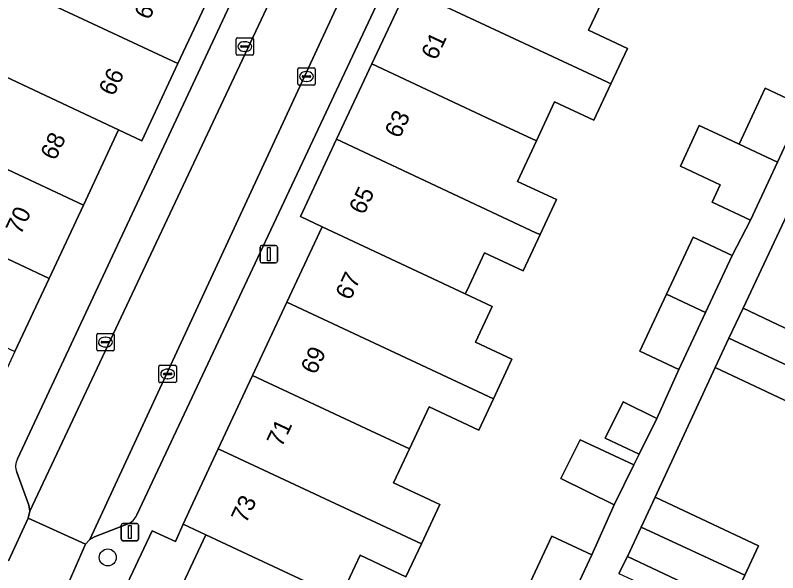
# Model space of a CAD drawing. Extents: x 159817 to 160765, y 380688 to 381638.
# Drawn here: x 160176.21 to 160219.96, y 381290.64 to 381322.59 of the extents above; entities that cross this region are included whole.
import ezdxf

# ---------------------------------------------------------------- set-up
doc = ezdxf.new("R2010")
doc.units = 0
for name, color, linetype in [('IMGEO_Boom', 7, 'Continuous'), ('IMGEO_Erf', 7, 'Continuous'), ('IMGEO_Kolk', 7, 'Continuous'), ('IMGEO_Lichtmast', 7, 'Continuous'), ('IMGEO_Pand', 7, 'Continuous'), ('IMGEO_Pand_nummerreeks', 7, 'Continuous'), ('IMGEO_Parkeervlak_open', 7, 'Continuous'), ('IMGEO_Rijbaan_lokaal_open', 7, 'Continuous'), ('IMGEO_Voetpad_halfverhard', 7, 'Continuous'), ('IMGEO_Voetpad_open', 7, 'Continuous')]:
    doc.layers.add(name, color=color, linetype=linetype)

msp = doc.modelspace()

# ---------------------------------------------------------------- linework, layer by layer
at = {"layer": 'IMGEO_Boom'}
msp.add_circle((160181.516, 381291.514), 0.489, dxfattribs=at)
at = {"layer": 'IMGEO_Erf'}
for points in [[(160210.219, 381324.135), (160209.096, 381321.736), (160211.329, 381320.69), (160210.378, 381318.659), (160209.402, 381316.572), (160207.155, 381317.624), (160206.109, 381315.388), (160205.024, 381313.07), (160207.262, 381312.023), (160206.323, 381310.016), (160205.351, 381307.94), (160203.135, 381308.978), (160202.134, 381306.839), (160202.032, 381306.621), (160203.579, 381305.897), (160202.621, 381303.849), (160204.701, 381302.875), (160203.64, 381300.609), (160202.801, 381298.816), (160199.952, 381300.149), (160198.823, 381297.736), (160197.91, 381295.786), (160200.564, 381294.544), (160199.508, 381292.288), (160198.627, 381290.404), (160195.996, 381291.635), (160194.857, 381289.201)], [(160205.49, 381289.504), (160206.996, 381292.73), (160209.288, 381291.66), (160210.564, 381294.523), (160207.515, 381296.031), (160208.619, 381298.262), (160211.7, 381296.821), (160212.003, 381297.433), (160210.062, 381298.341), (160211.094, 381300.43), (160213.015, 381299.48), (160214.292, 381302.283), (160212.052, 381303.329), (160213.58, 381306.604), (160215.101, 381309.866), (160217.343, 381308.82), (160218.39, 381310.842), (160216.188, 381311.87), (160216.657, 381312.876), (160214.37, 381313.946), (160215.456, 381316.273), (160217.053, 381315.525), (160217.743, 381315.202), (160219.238, 381318.406), (160221.44, 381317.379)], [(160221.405, 381313.09), (160217.965, 381305.792), (160223.888, 381303.001)], [(160222.288, 381299.605), (160216.365, 381302.397), (160212.932, 381294.963), (160218.855, 381292.172), (160218.063, 381290.492), (160217.255, 381288.776), (160211.332, 381291.567), (160210.842, 381290.6), (160212.59, 381289.786), (160211.501, 381287.444), (160209.752, 381288.257), (160207.732, 381284.025), (160213.443, 381281.353), (160212.775, 381279.925), (160212.092, 381278.466), (160206.381, 381281.138), (160205.548, 381279.354), (160209.884, 381277.322), (160208.887, 381275.196), (160204.6, 381277.205), (160204.565, 381277.114), (160225.954, 381267.134)]]:
    msp.add_lwpolyline(points, dxfattribs=at)
msp.add_lwpolyline([(160190.736, 381283.488), (160191.63, 381285.397), (160185.096, 381288.454), (160187.137, 381292.815), (160185.833, 381293.425), (160185.402, 381292.422), (160184.059, 381293.029), (160182.154, 381288.991), (160182.804, 381287.168)], close=True, dxfattribs=at)
at = {"layer": 'IMGEO_Kolk'}
for p, q in [((160188.881, 381320.372), (160188.881, 381321.224)), ((160188.956, 381321.298), (160189.808, 381321.298)), ((160189.882, 381321.224), (160189.882, 381320.372)), ((160189.14, 381320.792), (160189.14, 381320.804)), ((160189.578, 381320.755), (160189.18, 381320.755)), ((160189.183, 381320.841), (160189.581, 381320.841)), ((160189.369, 381321.078), (160189.394, 381321.078)), ((160189.624, 381320.804), (160189.624, 381320.792)), ((160189.808, 381320.298), (160188.956, 381320.298)), ((160189.392, 381320.518), (160189.367, 381320.518)), ((160192.415, 381318.657), (160192.415, 381319.509)), ((160192.49, 381319.583), (160193.342, 381319.583)), ((160192.903, 381319.363), (160192.928, 381319.363)), ((160193.416, 381319.509), (160193.416, 381318.657)), ((160192.674, 381319.077), (160192.674, 381319.089)), ((160193.112, 381319.04), (160192.714, 381319.04)), ((160192.717, 381319.126), (160193.115, 381319.126)), ((160193.158, 381319.089), (160193.158, 381319.077)), ((160193.342, 381318.583), (160192.49, 381318.583)), ((160192.926, 381318.803), (160192.901, 381318.803)), ((160180.879, 381303.429), (160180.879, 381304.281)), ((160180.954, 381304.355), (160181.806, 381304.355)), ((160181.367, 381304.135), (160181.392, 381304.135)), ((160181.88, 381304.281), (160181.88, 381303.429)), ((160181.138, 381303.849), (160181.138, 381303.861)), ((160181.576, 381303.812), (160181.178, 381303.812)), ((160181.181, 381303.898), (160181.579, 381303.898)), ((160181.622, 381303.861), (160181.622, 381303.849)), ((160181.806, 381303.355), (160180.954, 381303.355)), ((160181.39, 381303.575), (160181.365, 381303.575)), ((160184.45, 381301.605), (160184.45, 381302.457)), ((160184.525, 381302.531), (160185.377, 381302.531)), ((160184.938, 381302.311), (160184.963, 381302.311)), ((160185.451, 381302.457), (160185.451, 381301.605)), ((160184.709, 381302.025), (160184.709, 381302.037)), ((160185.147, 381301.988), (160184.749, 381301.988)), ((160184.752, 381302.074), (160185.15, 381302.074)), ((160185.193, 381302.037), (160185.193, 381302.025)), ((160185.377, 381301.531), (160184.525, 381301.531)), ((160184.961, 381301.751), (160184.936, 381301.751))]:
    msp.add_line(p, q, dxfattribs=at)
for points in [[(160188.881, 381320.372), (160188.881, 381321.224)], [(160188.956, 381321.298), (160189.808, 381321.298)], [(160189.882, 381321.224), (160189.882, 381320.372)], [(160189.808, 381320.298), (160188.956, 381320.298)], [(160192.415, 381318.657), (160192.415, 381319.509)], [(160192.49, 381319.583), (160193.342, 381319.583)], [(160193.416, 381319.509), (160193.416, 381318.657)], [(160193.342, 381318.583), (160192.49, 381318.583)], [(160180.879, 381303.429), (160180.879, 381304.281)], [(160180.954, 381304.355), (160181.806, 381304.355)], [(160181.88, 381304.281), (160181.88, 381303.429)], [(160181.806, 381303.355), (160180.954, 381303.355)], [(160184.45, 381301.605), (160184.45, 381302.457)], [(160184.525, 381302.531), (160185.377, 381302.531)], [(160185.451, 381302.457), (160185.451, 381301.605)], [(160185.377, 381301.531), (160184.525, 381301.531)]]:
    msp.add_lwpolyline(points, dxfattribs=at)
for centre, radius, start, end in [((160188.958, 381321.222), 0.0765, 91.552, 178.448), ((160188.958, 381321.222), 0.0765, 91.552, 178.448), ((160189.806, 381321.222), 0.0765, 1.552, 88.448), ((160189.806, 381321.222), 0.0765, 1.552, 88.448), ((160189.18, 381320.801), 0.0403, 85.8775, 175.7526), ((160189.177, 381320.791), 0.0366, 178.938, 274.7102), ((160189.581, 381320.798), 0.043, 264.8664, 352.4533), ((160189.585, 381320.803), 0.0386, 1.7309, 96.639), ((160188.958, 381320.374), 0.0765, 181.552, 268.448), ((160188.958, 381320.374), 0.0765, 181.552, 268.448), ((160189.806, 381320.374), 0.0765, 271.552, 358.448), ((160189.806, 381320.374), 0.0765, 271.552, 358.448), ((160192.492, 381319.507), 0.0765, 91.552, 178.448), ((160192.492, 381319.507), 0.0765, 91.552, 178.448), ((160193.34, 381319.507), 0.0765, 1.552, 88.448), ((160193.34, 381319.507), 0.0765, 1.552, 88.448), ((160192.714, 381319.086), 0.0403, 85.8775, 175.7526), ((160192.711, 381319.076), 0.0366, 178.938, 274.7102), ((160193.115, 381319.083), 0.043, 264.8664, 352.4533), ((160193.119, 381319.088), 0.0386, 1.7309, 96.639), ((160192.492, 381318.659), 0.0765, 181.552, 268.448), ((160192.492, 381318.659), 0.0765, 181.552, 268.448), ((160193.34, 381318.659), 0.0765, 271.552, 358.448), ((160193.34, 381318.659), 0.0765, 271.552, 358.448), ((160180.956, 381304.279), 0.0765, 91.552, 178.448), ((160180.956, 381304.279), 0.0765, 91.552, 178.448), ((160181.804, 381304.279), 0.0765, 1.552, 88.448), ((160181.804, 381304.279), 0.0765, 1.552, 88.448), ((160181.178, 381303.858), 0.0403, 85.8775, 175.7526), ((160181.175, 381303.848), 0.0366, 178.938, 274.7102), ((160181.579, 381303.855), 0.043, 264.8664, 352.4533), ((160181.583, 381303.86), 0.0386, 1.7309, 96.639), ((160180.956, 381303.431), 0.0765, 181.552, 268.448), ((160180.956, 381303.431), 0.0765, 181.552, 268.448), ((160181.804, 381303.431), 0.0765, 271.552, 358.448), ((160181.804, 381303.431), 0.0765, 271.552, 358.448), ((160184.527, 381302.455), 0.0765, 91.552, 178.448), ((160184.527, 381302.455), 0.0765, 91.552, 178.448), ((160185.375, 381302.455), 0.0765, 1.552, 88.448), ((160185.375, 381302.455), 0.0765, 1.552, 88.448), ((160184.749, 381302.034), 0.0403, 85.8775, 175.7526), ((160184.746, 381302.024), 0.0366, 178.938, 274.7102), ((160185.15, 381302.031), 0.043, 264.8664, 352.4533), ((160185.154, 381302.036), 0.0386, 1.7309, 96.639), ((160184.527, 381301.607), 0.0765, 181.552, 268.448), ((160184.527, 381301.607), 0.0765, 181.552, 268.448), ((160185.375, 381301.607), 0.0765, 271.552, 358.448), ((160185.375, 381301.607), 0.0765, 271.552, 358.448)]:
    msp.add_arc(centre, radius, start, end, dxfattribs=at)
for centre, major_axis, ratio, start_param, end_param in [((160189.368, 381320.798), (-0.387, 0.002), 0.722429, 4.712389, 7.853982), ((160189.393, 381320.798), (-0.39, 0.002), 0.717154, 1.570796, 4.712389), ((160192.902, 381319.083), (-0.387, 0.002), 0.722429, 4.712389, 7.853982), ((160192.927, 381319.083), (-0.39, 0.002), 0.717154, 1.570796, 4.712389), ((160181.366, 381303.855), (-0.387, 0.002), 0.722429, 4.712389, 7.853982), ((160181.391, 381303.855), (-0.39, 0.002), 0.717154, 1.570796, 4.712389), ((160184.937, 381302.031), (-0.387, 0.002), 0.722429, 4.712389, 7.853982), ((160184.962, 381302.031), (-0.39, 0.002), 0.717154, 1.570796, 4.712389)]:
    msp.add_ellipse(centre, major_axis=major_axis, ratio=ratio, start_param=start_param, end_param=end_param, dxfattribs=at)
at = {"layer": 'IMGEO_Lichtmast'}
for p, q in [((160190.258, 381308.498), (160190.258, 381309.298)), ((160190.258, 381309.298), (160190.258, 381308.498)), ((160190.358, 381309.398), (160191.148, 381309.398)), ((160191.148, 381309.398), (160190.358, 381309.398)), ((160191.248, 381309.298), (160191.248, 381308.498)), ((160191.248, 381308.498), (160191.248, 381309.298)), ((160191.148, 381308.398), (160190.358, 381308.398)), ((160190.358, 381308.398), (160191.148, 381308.398)), ((160182.283, 381292.566), (160182.283, 381293.366)), ((160182.283, 381293.366), (160182.283, 381292.566)), ((160182.383, 381293.466), (160183.173, 381293.466)), ((160183.173, 381293.466), (160182.383, 381293.466)), ((160183.273, 381293.366), (160183.273, 381292.566)), ((160183.273, 381292.566), (160183.273, 381293.366)), ((160183.173, 381292.466), (160182.383, 381292.466)), ((160182.383, 381292.466), (160183.173, 381292.466))]:
    msp.add_line(p, q, dxfattribs=at)
for points in [[(160190.678, 381309.273), (160190.828, 381309.273), (160190.828, 381308.523), (160190.678, 381308.523), (160190.678, 381309.273)], [(160182.703, 381293.341), (160182.853, 381293.341), (160182.853, 381292.591), (160182.703, 381292.591), (160182.703, 381293.341)]]:
    msp.add_lwpolyline(points, dxfattribs=at)
for centre, start, end in [((160190.358, 381309.298), 90, 180), ((160190.358, 381309.298), 90, 180), ((160191.148, 381309.298), 0, 90), ((160191.148, 381309.298), 360, 90), ((160190.358, 381308.498), 180, 270), ((160190.358, 381308.498), 180, 270), ((160191.148, 381308.498), 270, 0), ((160191.148, 381308.498), 270, 0), ((160182.383, 381293.366), 90, 180), ((160182.383, 381293.366), 90, 180), ((160183.173, 381293.366), 0, 90), ((160183.173, 381293.366), 360, 90), ((160182.383, 381292.566), 180, 270), ((160182.383, 381292.566), 180, 270), ((160183.173, 381292.566), 270, 0), ((160183.173, 381292.566), 270, 0)]:
    msp.add_arc(centre, 0.1, start, end, dxfattribs=at)
at = {"layer": 'IMGEO_Pand'}
for points in [[(160173.791, 381325.318), (160185.534, 381319.826), (160187.554, 381324.142), (160180.701, 381327.347), (160178.108, 381328.56), (160177.087, 381326.378), (160174.79, 381327.453)], [(160203.421, 381327.319), (160200.76, 381328.565), (160198.686, 381324.132), (160210.143, 381318.769), (160210.378, 381318.659), (160211.329, 381320.69), (160209.096, 381321.736), (160210.219, 381324.135)], [(160185.534, 381319.826), (160173.791, 381325.318), (160172.873, 381323.355), (160174.016, 381322.82), (160172.867, 381320.363), (160175.321, 381319.214), (160182.134, 381316.022), (160183.463, 381315.401)], [(160210.378, 381318.659), (160210.143, 381318.769), (160198.686, 381324.132), (160196.663, 381319.809), (160203.273, 381316.715), (160206.109, 381315.388), (160207.155, 381317.624), (160209.402, 381316.572)], [(160180.118, 381311.714), (160182.134, 381316.022), (160175.321, 381319.214), (160172.867, 381320.363), (160171.913, 381318.324), (160169.419, 381319.491), (160168.355, 381317.216)], [(160206.109, 381315.388), (160203.273, 381316.715), (160196.663, 381319.809), (160194.64, 381315.486), (160206.082, 381310.129), (160206.323, 381310.016), (160207.262, 381312.023), (160205.024, 381313.07)], [(160221.44, 381317.379), (160219.238, 381318.406), (160217.743, 381315.202), (160219.944, 381314.171)], [(160180.118, 381311.714), (160168.355, 381317.216), (160167.509, 381315.409), (160170.003, 381314.242), (160168.883, 381311.848), (160171.315, 381310.71), (160178.152, 381307.511)], [(160219.944, 381314.171), (160217.743, 381315.202), (160217.053, 381315.525), (160215.456, 381316.273), (160214.37, 381313.946), (160216.657, 381312.876), (160216.188, 381311.87), (160218.39, 381310.842)], [(160206.323, 381310.016), (160206.082, 381310.129), (160194.64, 381315.486), (160192.567, 381311.056), (160193.81, 381310.472), (160200.477, 381307.349), (160202.032, 381306.621), (160202.134, 381306.839), (160203.135, 381308.978), (160205.351, 381307.94)], [(160178.152, 381307.511), (160171.315, 381310.71), (160168.883, 381311.848), (160167.848, 381309.637), (160165.326, 381310.817), (160164.394, 381308.825), (160176.186, 381303.309)], [(160203.579, 381305.897), (160202.032, 381306.621), (160200.477, 381307.349), (160193.81, 381310.472), (160191.789, 381306.154), (160203.64, 381300.609), (160204.701, 381302.875), (160202.621, 381303.849)], [(160217.343, 381308.82), (160215.101, 381309.866), (160213.58, 381306.604), (160215.819, 381305.555)], [(160215.819, 381305.555), (160213.58, 381306.604), (160212.052, 381303.329), (160214.292, 381302.283)], [(160191.789, 381306.154), (160189.821, 381301.947), (160196.61, 381298.771), (160198.823, 381297.736), (160199.952, 381300.149), (160202.801, 381298.816), (160203.64, 381300.609)], [(160217.159, 381304.082), (160223.096, 381301.32), (160223.888, 381303.001), (160217.965, 381305.792)], [(160217.159, 381304.082), (160216.365, 381302.397), (160222.288, 381299.605), (160223.096, 381301.32)], [(160189.821, 381301.947), (160187.852, 381297.739), (160199.508, 381292.288), (160200.564, 381294.544), (160197.91, 381295.786), (160198.823, 381297.736), (160196.61, 381298.771)], [(160213.015, 381299.48), (160211.094, 381300.43), (160210.062, 381298.341), (160212.003, 381297.433)], [(160211.7, 381296.821), (160208.619, 381298.262), (160207.515, 381296.031), (160210.564, 381294.523)], [(160199.508, 381292.288), (160187.852, 381297.739), (160186.396, 381294.628), (160185.833, 381293.425), (160187.137, 381292.815), (160194.01, 381289.597), (160194.857, 381289.201), (160195.996, 381291.635), (160198.627, 381290.404)], [(160212.126, 381293.252), (160218.063, 381290.492), (160218.855, 381292.172), (160212.932, 381294.963)], [(160212.126, 381293.252), (160211.332, 381291.567), (160217.255, 381288.776), (160218.063, 381290.492)], [(160195.304, 381288.991), (160194.857, 381289.201), (160194.01, 381289.597), (160187.137, 381292.815), (160185.096, 381288.454), (160191.63, 381285.397), (160190.736, 381283.488), (160195.026, 381281.48), (160196.819, 381285.312), (160194.163, 381286.554)], [(160209.288, 381291.66), (160206.996, 381292.73), (160205.49, 381289.504), (160207.782, 381288.432)]]:
    msp.add_lwpolyline(points, close=True, dxfattribs=at)
at = {"layer": 'IMGEO_Parkeervlak_open'}
for points in [[(160176.294, 381296.399), (160176.994, 381294.516), (160177.045, 381294.172), (160192.165, 381326.293), (160194.454, 381329.73), (160190.656, 381327.455), (160190.33, 381327.067), (160176.341, 381297.159)], [(160183.191, 381293.955), (160197.656, 381324.738), (160197.726, 381325.089), (160197.373, 381327.04), (160197.381, 381327.399), (160196.193, 381325.998), (160195.339, 381324.582), (160180.486, 381292.549), (160180.753, 381292.697), (160182.637, 381293.415)]]:
    msp.add_lwpolyline(points, dxfattribs=at)
for centre, radius, start, end in [((160177.07, 381296.732), 0.844, 149.6623, 203.2601), ((160182.215, 381294.402), 1.073, 293.1395, 335.3941)]:
    msp.add_arc(centre, radius, start, end, dxfattribs=at)
at = {"layer": 'IMGEO_Rijbaan_lokaal_open'}
msp.add_lwpolyline([(160194.454, 381329.73), (160192.165, 381326.293), (160177.045, 381294.172), (160176.954, 381293.771), (160180.244, 381292.279), (160180.486, 381292.549), (160195.339, 381324.582), (160196.193, 381325.998), (160197.381, 381327.399), (160197.544, 381327.742), (160194.732, 381329.969)], close=True, dxfattribs=at)
msp.add_lwpolyline([(160179.298, 381290.141), (160180.244, 381292.279), (160176.954, 381293.771), (160175.818, 381291.324)], dxfattribs=at)
at = {"layer": 'IMGEO_Voetpad_halfverhard'}
for points in [[(160221.44, 381317.379), (160219.944, 381314.171), (160218.39, 381310.842), (160217.343, 381308.82), (160215.819, 381305.555), (160214.292, 381302.283), (160213.015, 381299.48), (160212.003, 381297.433), (160211.7, 381296.821), (160210.564, 381294.523), (160209.288, 381291.66), (160207.782, 381288.432)], [(160210.842, 381290.6), (160211.332, 381291.567), (160212.126, 381293.252), (160212.932, 381294.963), (160216.365, 381302.397), (160217.159, 381304.082), (160217.965, 381305.792), (160221.405, 381313.09)]]:
    msp.add_lwpolyline(points, dxfattribs=at)
at = {"layer": 'IMGEO_Voetpad_open'}
for points in [[(160176.341, 381297.159), (160190.33, 381327.067), (160190.656, 381327.455), (160194.454, 381329.73), (160194.732, 381329.969), (160195.021, 381330.217), (160196.888, 381332.562)], [(160202.829, 381332.847), (160201.048, 381331.963), (160200.708, 381331.706), (160199.639, 381330.369), (160197.544, 381327.742), (160197.381, 381327.399), (160197.373, 381327.04), (160197.726, 381325.089), (160197.656, 381324.738), (160183.191, 381293.955)], [(160187.554, 381324.142), (160185.534, 381319.826), (160183.463, 381315.401), (160182.134, 381316.022), (160180.118, 381311.714), (160178.152, 381307.511), (160176.186, 381303.309), (160174.73, 381300.197), (160174.168, 381298.997), (160173.629, 381297.876), (160174.985, 381297.226), (160173.102, 381293.237), (160171.277, 381292.584), (160175.381, 381290.671)], [(160178.992, 381288.981), (160182.804, 381287.168), (160182.154, 381288.991), (160184.059, 381293.029), (160185.402, 381292.422), (160185.833, 381293.425), (160186.396, 381294.628), (160187.852, 381297.739), (160189.821, 381301.947), (160191.789, 381306.154), (160193.81, 381310.472), (160192.567, 381311.056), (160194.64, 381315.486), (160196.663, 381319.809), (160198.686, 381324.132)], [(160175.818, 381291.324), (160176.954, 381293.771), (160177.045, 381294.172), (160176.994, 381294.516), (160176.294, 381296.399)], [(160182.637, 381293.415), (160180.753, 381292.697), (160180.486, 381292.549), (160180.244, 381292.279), (160179.298, 381290.141)]]:
    msp.add_lwpolyline(points, dxfattribs=at)
for centre, radius, start, end in [((160177.07, 381296.732), 0.844, 149.6623, 203.2601), ((160182.215, 381294.402), 1.073, 293.1395, 335.3941)]:
    msp.add_arc(centre, radius, start, end, dxfattribs=at)

# ---------------------------------------------------------------- texts
at = {"layer": 'IMGEO_Pand_nummerreeks'}
for s, rotation, p in [('64', 64.921, (160183.898, 381322.275)), ('61', 64.9237, (160200.356, 381319.963)), ('66', 64.9218, (160181.853, 381317.905)), ('63', 64.9237, (160198.26, 381315.484)), ('68', 64.9251, (160178.507, 381314.217)), ('65', 64.9218, (160196.212, 381311.106)), ('70', 64.9251, (160176.515, 381309.961)), ('67', 64.9218, (160195.434, 381306.204)), ('69', 64.923, (160193.44, 381301.942)), ('71', 64.923, (160191.493, 381297.782)), ('73', 64.9218, (160189.451, 381293.417))]:
    msp.add_text(s, height=1, rotation=rotation, dxfattribs=at).set_placement(p)

doc.saveas('drawing.dxf')
